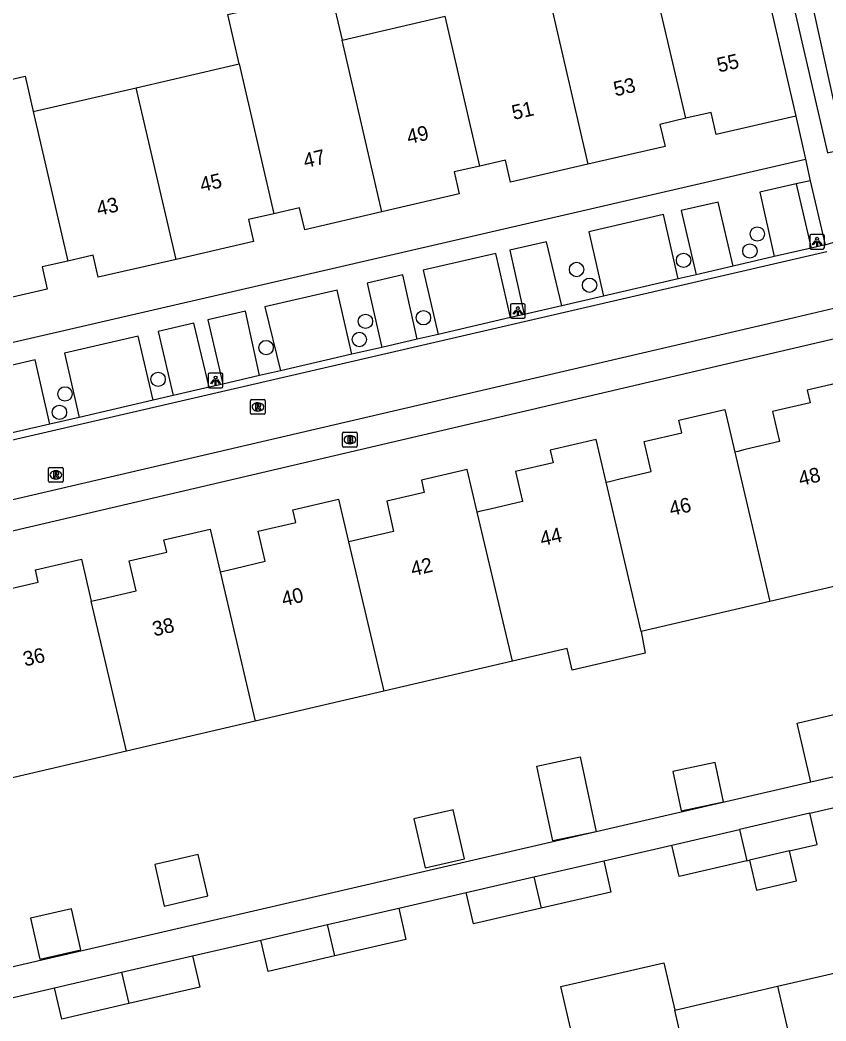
# Model space of a CAD drawing. Extents: x 156414 to 157775, y 382335 to 383765.
# Drawn here: x 156870.8 to 156925.8, y 382800.7 to 382868.8 of the extents above; entities that cross this region are included whole.
import ezdxf

# ---------------------------------------------------------------- set-up
doc = ezdxf.new("R2010")
doc.units = 0
for name, color, linetype in [('IMGEO_Boom', 7, 'Continuous'), ('IMGEO_Brandkraan', 7, 'Continuous'), ('IMGEO_Greppel_droge_sloot', 7, 'Continuous'), ('IMGEO_Lichtpunt', 7, 'Continuous'), ('IMGEO_Pand', 7, 'Continuous'), ('IMGEO_Pand_nummerreeks', 7, 'Continuous'), ('IMGEO_Rijbaan_lokaal_gesloten', 7, 'Continuous'), ('IMGEO_Rijbaan_lokaal_open', 7, 'Continuous'), ('IMGEO_Rioolput', 7, 'Continuous'), ('IMGEO_Voetpad_open', 7, 'Continuous')]:
    doc.layers.add(name, color=color, linetype=linetype)

msp = doc.modelspace()

# ---------------------------------------------------------------- linework, layer by layer
at = {"layer": 'IMGEO_Boom'}
for centre in [(156921.071, 382854.259), (156920.564, 382853.097), (156916.047, 382852.464), (156908.759, 382851.838), (156909.641, 382850.77), (156894.376, 382848.311), (156898.324, 382848.554), (156893.96, 382847.07), (156887.605, 382846.519), (156880.252, 382844.36), (156873.905, 382843.364), (156873.528, 382842.108)]:
    msp.add_circle(centre, 0.489, dxfattribs=at)
at = {"layer": 'IMGEO_Brandkraan'}
for p, q in [((156892.816, 382839.823), (156892.816, 382840.675)), ((156892.891, 382840.749), (156893.743, 382840.749)), ((156893.304, 382840.529), (156893.329, 382840.529)), ((156893.817, 382840.675), (156893.817, 382839.823)), ((156893.743, 382839.749), (156892.891, 382839.749)), ((156893.327, 382839.969), (156893.302, 382839.969))]:
    msp.add_line(p, q, dxfattribs=at)
for points in [[(156892.816, 382839.823), (156892.816, 382840.675)], [(156892.891, 382840.749), (156893.743, 382840.749)], [(156893.164, 382840.449), (156893.164, 382840.049), (156893.377, 382840.049)], [(156893.395, 382840.449), (156893.164, 382840.449)], [(156893.343, 382840.368), (156893.289, 382840.368), (156893.289, 382840.292)], [(156893.289, 382840.292), (156893.342, 382840.292)], [(156893.817, 382840.675), (156893.817, 382839.823)], [(156893.743, 382839.749), (156892.891, 382839.749)], [(156893.351, 382840.216), (156893.289, 382840.216), (156893.289, 382840.135)], [(156893.289, 382840.135), (156893.351, 382840.135)]]:
    msp.add_lwpolyline(points, dxfattribs=at)
for centre, radius, start, end in [((156892.893, 382840.673), 0.0765, 91.55205, 178.44795), ((156892.893, 382840.673), 0.0765, 91.55205, 178.44795), ((156893.344, 382840.33), 0.0379, 267.82845, 90.93552), ((156893.399, 382840.304), 0.145, 59.4692, 91.53667), ((156893.424, 382840.351), 0.0922, 285.51372, 58.15012), ((156893.429, 382840.159), 0.105, 301.31148, 78.98903), ((156893.741, 382840.673), 0.0765, 1.55205, 88.44795), ((156893.741, 382840.673), 0.0765, 1.55205, 88.44795), ((156892.893, 382839.825), 0.0765, 181.55205, 268.44795), ((156892.893, 382839.825), 0.0765, 181.55205, 268.44795), ((156893.352, 382840.175), 0.0404, 269.87594, 90.50774), ((156893.383, 382840.3), 0.251, 268.66757, 293.53466), ((156893.741, 382839.825), 0.0765, 271.55205, 358.44795), ((156893.741, 382839.825), 0.0765, 271.55205, 358.44795)]:
    msp.add_arc(centre, radius, start, end, dxfattribs=at)
for centre, major_axis, ratio, start_param, end_param in [((156893.303, 382840.249), (-0.387, 0.002), 0.722429, 4.712389, 7.853982), ((156893.328, 382840.249), (-0.39, 0.002), 0.717154, 1.570796, 4.712389)]:
    msp.add_ellipse(centre, major_axis=major_axis, ratio=ratio, start_param=start_param, end_param=end_param, dxfattribs=at)
at = {"layer": 'IMGEO_Greppel_droge_sloot'}
msp.add_lwpolyline([(156928.493, 382863.788), (156926.278, 382863.313), (156915.815, 382910.793), (156917.946, 382911.213), (156924.219, 382883.281), (156928.493, 382863.788)], dxfattribs=at)
at = {"layer": 'IMGEO_Lichtpunt'}
for p, q in [((156924.645, 382854.133), (156924.645, 382853.326)), ((156924.645, 382854.133), (156924.645, 382853.326)), ((156925.547, 382854.228), (156924.739, 382854.228)), ((156925.547, 382854.228), (156924.739, 382854.228)), ((156925.641, 382853.326), (156925.641, 382854.133)), ((156925.641, 382853.326), (156925.641, 382854.133)), ((156924.739, 382853.232), (156925.547, 382853.232)), ((156924.739, 382853.232), (156925.547, 382853.232)), ((156904.256, 382849.415), (156904.256, 382848.608)), ((156904.256, 382849.415), (156904.256, 382848.608)), ((156905.158, 382849.51), (156904.35, 382849.51)), ((156905.158, 382849.51), (156904.35, 382849.51)), ((156905.252, 382848.608), (156905.252, 382849.415)), ((156905.252, 382848.608), (156905.252, 382849.415)), ((156904.35, 382848.514), (156905.158, 382848.514)), ((156904.35, 382848.514), (156905.158, 382848.514)), ((156883.663, 382844.678), (156883.663, 382843.871)), ((156883.663, 382844.678), (156883.663, 382843.871)), ((156884.565, 382844.773), (156883.757, 382844.773)), ((156884.565, 382844.773), (156883.757, 382844.773)), ((156884.659, 382843.871), (156884.659, 382844.678)), ((156884.659, 382843.871), (156884.659, 382844.678)), ((156883.757, 382843.777), (156884.565, 382843.777)), ((156883.757, 382843.777), (156884.565, 382843.777))]:
    msp.add_line(p, q, dxfattribs=at)
for points in [[(156925.019, 382853.797), (156925.058, 382853.769), (156924.87, 382853.507), (156924.832, 382853.534), (156925.019, 382853.797)], [(156925.121, 382853.749), (156925.168, 382853.749), (156925.168, 382853.427), (156925.121, 382853.427), (156925.121, 382853.749)], [(156925.231, 382853.769), (156925.269, 382853.796), (156925.456, 382853.534), (156925.417, 382853.506), (156925.231, 382853.769)], [(156904.63, 382849.079), (156904.669, 382849.051), (156904.481, 382848.789), (156904.443, 382848.816), (156904.63, 382849.079)], [(156904.732, 382849.031), (156904.779, 382849.031), (156904.779, 382848.709), (156904.732, 382848.709), (156904.732, 382849.031)], [(156904.842, 382849.051), (156904.88, 382849.078), (156905.067, 382848.816), (156905.028, 382848.788), (156904.842, 382849.051)], [(156884.037, 382844.342), (156884.076, 382844.314), (156883.888, 382844.052), (156883.85, 382844.079), (156884.037, 382844.342)], [(156884.249, 382844.314), (156884.287, 382844.341), (156884.474, 382844.079), (156884.435, 382844.051), (156884.249, 382844.314)], [(156884.139, 382844.294), (156884.186, 382844.294), (156884.186, 382843.972), (156884.139, 382843.972), (156884.139, 382844.294)]]:
    msp.add_lwpolyline(points, dxfattribs=at)
for centre in [(156925.144, 382853.931), (156904.755, 382849.213), (156884.162, 382844.476)]:
    msp.add_circle(centre, 0.0994, dxfattribs=at)
for centre, start, end in [((156924.739, 382854.133), 90, 180), ((156924.739, 382854.133), 90, 180), ((156925.547, 382854.133), 0, 90), ((156925.547, 382854.133), 0, 90), ((156924.739, 382853.326), 180, 270), ((156924.739, 382853.326), 180, 270), ((156925.547, 382853.326), 270, 0), ((156925.547, 382853.326), 270, 360), ((156904.35, 382849.415), 90, 180), ((156904.35, 382849.415), 90, 180), ((156905.158, 382849.415), 0, 90), ((156905.158, 382849.415), 0, 90), ((156904.35, 382848.608), 180, 270), ((156904.35, 382848.608), 180, 270), ((156905.158, 382848.608), 270, 0), ((156905.158, 382848.608), 270, 360), ((156883.757, 382844.678), 90, 180), ((156883.757, 382844.678), 90, 180), ((156884.565, 382844.678), 0, 90), ((156884.565, 382844.678), 0, 90), ((156883.757, 382843.871), 180, 270), ((156883.757, 382843.871), 180, 270), ((156884.565, 382843.871), 270, 0), ((156884.565, 382843.871), 270, 360)]:
    msp.add_arc(centre, 0.0946, start, end, dxfattribs=at)
at = {"layer": 'IMGEO_Pand'}
for points in [[(156920.983, 382873.977), (156923.698, 382862.279)], [(156916.198, 382862.134), (156913.825, 382872.323)], [(156885.771, 382865.841), (156884.991, 382869.213), (156892.002, 382870.835), (156892.785, 382867.461)], [(156906.812, 382870.703), (156909.525, 382859.004)], [(156892.785, 382867.461), (156899.798, 382869.082)], [(156902.17, 382858.884), (156899.798, 382869.082)], [(156895.499, 382855.764), (156892.785, 382867.461)], [(156878.757, 382864.22), (156885.771, 382865.841)], [(156885.771, 382865.841), (156888.131, 382855.638)], [(156864.73, 382860.979), (156864.176, 382863.373), (156871.189, 382864.996), (156871.744, 382862.599)], [(156871.744, 382862.599), (156878.757, 382864.22)], [(156881.472, 382852.525), (156878.757, 382864.22)], [(156871.744, 382862.599), (156874.101, 382852.413)], [(156916.198, 382862.134), (156914.437, 382861.725), (156914.785, 382860.225), (156909.525, 382859.004)], [(156923.698, 382862.279), (156918.273, 382861.034), (156917.925, 382862.535), (156916.198, 382862.134)], [(156902.17, 382858.884), (156900.41, 382858.482), (156900.758, 382856.982), (156895.499, 382855.764)], [(156909.525, 382859.004), (156904.262, 382857.782), (156903.914, 382859.282), (156902.17, 382858.884)], [(156895.499, 382855.764), (156890.24, 382854.546), (156889.893, 382856.046), (156888.131, 382855.638)], [(156888.131, 382855.638), (156886.405, 382855.239), (156886.753, 382853.738), (156881.472, 382852.525)], [(156881.472, 382852.525), (156876.163, 382851.306), (156875.818, 382852.806), (156874.101, 382852.413)], [(156874.101, 382852.413), (156872.343, 382852.01), (156872.69, 382850.509), (156867.434, 382849.292)], [(156927.788, 382844.392), (156924.464, 382843.616), (156924.664, 382842.759), (156922.103, 382842.162), (156922.58, 382840.117), (156920.242, 382839.571), (156919.736, 382839.453), (156919.531, 382839.405)], [(156910.781, 382837.356), (156911.003, 382837.408), (156911.695, 382837.571), (156913.846, 382838.076), (156913.366, 382840.12), (156915.927, 382840.721), (156915.726, 382841.578), (156918.85, 382842.311), (156919.531, 382839.405)], [(156910.781, 382837.356), (156910.101, 382840.268), (156906.957, 382839.533), (156907.158, 382838.676), (156904.597, 382838.078), (156905.075, 382836.033), (156902.877, 382835.519), (156902.231, 382835.368), (156901.988, 382835.311)], [(156919.531, 382839.405), (156921.915, 382829.231)], [(156901.988, 382835.311), (156901.301, 382838.221), (156898.186, 382837.5), (156898.385, 382836.643), (156895.822, 382836.05), (156896.296, 382834.004), (156894.3, 382833.542), (156893.451, 382833.345), (156893.227, 382833.293)], [(156913.155, 382827.194), (156910.781, 382837.356)], [(156884.473, 382831.247), (156884.71, 382831.302), (156885.471, 382831.48), (156887.553, 382831.965), (156887.077, 382834.01), (156889.638, 382834.608), (156889.438, 382835.465), (156892.545, 382836.189), (156893.227, 382833.293)], [(156904.385, 382825.154), (156901.988, 382835.311)], [(156875.698, 382829.25), (156875.9, 382829.296), (156876.422, 382829.415), (156878.747, 382829.944), (156878.28, 382831.992), (156880.845, 382832.576), (156880.649, 382833.434), (156883.79, 382834.15), (156884.473, 382831.247)], [(156893.227, 382833.293), (156895.625, 382823.117)], [(156866.935, 382827.191), (156867.151, 382827.241), (156867.738, 382827.376), (156869.996, 382827.897), (156869.524, 382829.944), (156872.086, 382830.535), (156871.889, 382831.393), (156875.024, 382832.117), (156875.698, 382829.25)], [(156884.473, 382831.247), (156886.866, 382821.08)], [(156930.84, 382831.306), (156921.915, 382829.231)], [(156878.096, 382819.04), (156875.698, 382829.25)], [(156921.915, 382829.231), (156913.155, 382827.194)], [(156913.155, 382827.194), (156913.44, 382825.7), (156908.457, 382824.541), (156908.113, 382826.021), (156904.385, 382825.154)], [(156904.385, 382825.154), (156895.625, 382823.117)], [(156895.625, 382823.117), (156886.866, 382821.08)], [(156924.725, 382816.92), (156923.79, 382820.948), (156926.665, 382821.615), (156927.6, 382817.588)], [(156886.866, 382821.08), (156878.096, 382819.04)], [(156878.096, 382819.04), (156869.326, 382817.001)], [(156910.089, 382813.546), (156907.132, 382812.917), (156906.049, 382818.014), (156909.006, 382818.642), (156910.089, 382813.546)], [(156915.323, 382817.649), (156915.892, 382814.972), (156918.773, 382815.585), (156918.204, 382818.262), (156915.323, 382817.649)], [(156927.6, 382817.588), (156924.725, 382816.92)], [(156897.681, 382814.428), (156898.452, 382811.093), (156901.129, 382811.711), (156900.359, 382815.046), (156897.681, 382814.428)], [(156924.651, 382814.81), (156919.855, 382813.702)], [(156923.265, 382812.238), (156925.145, 382812.672), (156924.651, 382814.81)], [(156915.259, 382812.64), (156919.855, 382813.702)], [(156919.855, 382813.702), (156920.351, 382811.565)], [(156920.351, 382811.565), (156915.752, 382810.503), (156915.259, 382812.64)], [(156880.02, 382811.313), (156880.672, 382808.488), (156883.631, 382809.171), (156882.978, 382811.996), (156881.026, 382811.545), (156880.02, 382811.313)], [(156923.265, 382812.238), (156920.55, 382811.611)], [(156920.55, 382811.611), (156921.026, 382809.562), (156923.74, 382810.192), (156923.265, 382812.238)], [(156905.843, 382810.464), (156910.611, 382811.566)], [(156910.611, 382811.566), (156911.103, 382809.434), (156906.335, 382808.333)], [(156920.351, 382811.565), (156920.55, 382811.611)], [(156901.237, 382809.4), (156905.843, 382810.464)], [(156905.843, 382810.464), (156906.335, 382808.333)], [(156906.335, 382808.333), (156901.729, 382807.27), (156901.237, 382809.4)], [(156871.551, 382807.654), (156872.195, 382804.867), (156874.983, 382805.51), (156874.339, 382808.298), (156871.551, 382807.654)], [(156891.793, 382807.218), (156896.638, 382808.337)], [(156896.638, 382808.337), (156897.131, 382806.203), (156892.289, 382805.084)], [(156887.245, 382806.167), (156891.793, 382807.218)], [(156892.289, 382805.084), (156891.793, 382807.218)], [(156892.289, 382805.084), (156887.738, 382804.033), (156887.245, 382806.167)], [(156877.753, 382803.974), (156882.588, 382805.091)], [(156882.588, 382805.091), (156883.082, 382802.956), (156878.25, 382801.84)], [(156908.428, 382799.782), (156907.686, 382802.997), (156914.697, 382804.615), (156915.442, 382801.401)], [(156922.45, 382803.019), (156929.471, 382804.64)], [(156873.186, 382802.919), (156877.753, 382803.974)], [(156877.753, 382803.974), (156878.25, 382801.84)], [(156878.25, 382801.84), (156873.679, 382800.784), (156873.186, 382802.919)], [(156915.442, 382801.401), (156922.45, 382803.019)], [(156922.45, 382803.019), (156925.163, 382791.326)], [(156917.48, 382792.603), (156915.442, 382801.401)]]:
    msp.add_lwpolyline(points, dxfattribs=at)
at = {"layer": 'IMGEO_Rijbaan_lokaal_gesloten'}
for points in [[(156704.67, 382802.003), (156706.623, 382802.451), (156776.982, 382818.697), (156816.178, 382827.739), (156855.39, 382836.785), (156925.817, 382853.068)], [(156926.664, 382849.268), (156923.197, 382848.454), (156856.378, 382832.904), (156817.084, 382823.811), (156780.281, 382815.295), (156707.464, 382798.538)]]:
    msp.add_lwpolyline(points, dxfattribs=at)
at = {"layer": 'IMGEO_Rijbaan_lokaal_open'}
for points in [[(156925.683, 382853.514), (156926.283, 382853.698), (156926.76, 382853.92), (156927.263, 382854.185), (156927.472, 382854.33)], [(156924.736, 382853.295), (156922.218, 382852.713)], [(156925.683, 382853.514), (156924.736, 382853.295)], [(156922.218, 382852.713), (156919.436, 382852.07)], [(156919.436, 382852.07), (156916.897, 382851.483)], [(156915.69, 382851.204), (156910.6, 382850.027)], [(156916.897, 382851.483), (156915.69, 382851.204)], [(156910.6, 382850.027), (156907.756, 382849.369)], [(156907.756, 382849.369), (156905.196, 382848.777)], [(156904.266, 382848.562), (156899.333, 382847.422)], [(156905.196, 382848.777), (156904.266, 382848.562)], [(156897.895, 382847.09), (156895.49, 382846.533)], [(156899.333, 382847.422), (156897.895, 382847.09)], [(156895.49, 382846.533), (156893.454, 382846.063)], [(156893.454, 382846.063), (156888.588, 382844.938)], [(156887.16, 382844.608), (156884.659, 382844.029)], [(156888.588, 382844.938), (156887.16, 382844.608)], [(156883.73, 382843.815), (156881.278, 382843.248)], [(156884.659, 382844.029), (156883.73, 382843.815)], [(156881.278, 382843.248), (156879.923, 382842.934)], [(156879.923, 382842.934), (156874.877, 382841.768)], [(156874.877, 382841.768), (156872.882, 382841.306)], [(156872.882, 382841.306), (156868.022, 382840.183)]]:
    msp.add_lwpolyline(points, dxfattribs=at)
at = {"layer": 'IMGEO_Rioolput'}
for p, q in [((156886.547, 382842.05), (156886.547, 382842.902)), ((156886.622, 382842.976), (156887.474, 382842.976)), ((156887.035, 382842.756), (156887.06, 382842.756)), ((156887.548, 382842.902), (156887.548, 382842.05)), ((156887.474, 382841.976), (156886.622, 382841.976)), ((156887.058, 382842.196), (156887.033, 382842.196)), ((156872.783, 382837.422), (156872.783, 382838.274)), ((156872.858, 382838.348), (156873.71, 382838.348)), ((156873.784, 382838.274), (156873.784, 382837.422)), ((156873.294, 382837.568), (156873.269, 382837.568)), ((156873.271, 382838.128), (156873.296, 382838.128)), ((156873.71, 382837.348), (156872.858, 382837.348))]:
    msp.add_line(p, q, dxfattribs=at)
for points in [[(156886.547, 382842.05), (156886.547, 382842.902)], [(156886.622, 382842.976), (156887.474, 382842.976)], [(156887.136, 382842.674), (156886.884, 382842.676), (156886.884, 382842.276)], [(156886.884, 382842.276), (156887.008, 382842.276), (156887.008, 382842.438), (156887.019, 382842.438)], [(156887.062, 382842.595), (156887.008, 382842.595), (156887.008, 382842.514)], [(156887.008, 382842.514), (156887.06, 382842.514)], [(156887.066, 382842.409), (156887.137, 382842.276), (156887.277, 382842.276), (156887.212, 382842.402)], [(156887.548, 382842.902), (156887.548, 382842.05)], [(156887.474, 382841.976), (156886.622, 382841.976)], [(156872.783, 382837.422), (156872.783, 382838.274)], [(156872.858, 382838.348), (156873.71, 382838.348)], [(156873.784, 382838.274), (156873.784, 382837.422)], [(156873.372, 382838.046), (156873.12, 382838.048), (156873.12, 382837.648)], [(156873.12, 382837.648), (156873.244, 382837.648), (156873.244, 382837.81), (156873.255, 382837.81)], [(156873.298, 382837.967), (156873.244, 382837.967), (156873.244, 382837.886)], [(156873.244, 382837.886), (156873.296, 382837.886)], [(156873.302, 382837.781), (156873.373, 382837.648), (156873.513, 382837.648), (156873.448, 382837.774)], [(156873.71, 382837.348), (156872.858, 382837.348)]]:
    msp.add_lwpolyline(points, dxfattribs=at)
for centre, radius, start, end in [((156886.624, 382842.9), 0.0765, 91.55205, 178.44795), ((156886.624, 382842.9), 0.0765, 91.55205, 178.44795), ((156887.018, 382842.385), 0.0533, 26.02933, 88.69889), ((156887.044, 382842.703), 0.19, 274.7715, 282.96867), ((156887.068, 382842.499), 0.0964, 77.00612, 93.18647), ((156887.082, 382842.556), 0.0378, 276.66336, 79.67722), ((156887.135, 382842.564), 0.109, 350.36119, 89.41601), ((156887.133, 382842.564), 0.112, 277.58423, 350.98172), ((156887.117, 382842.349), 0.108, 29.51342, 73.79051), ((156887.472, 382842.9), 0.0765, 1.55205, 88.44795), ((156887.472, 382842.9), 0.0765, 1.55205, 88.44795), ((156886.624, 382842.052), 0.0765, 181.55205, 268.44795), ((156886.624, 382842.052), 0.0765, 181.55205, 268.44795), ((156887.472, 382842.052), 0.0765, 271.55205, 358.44795), ((156887.472, 382842.052), 0.0765, 271.55205, 358.44795), ((156872.86, 382838.272), 0.0765, 91.55205, 178.44795), ((156872.86, 382838.272), 0.0765, 91.55205, 178.44795), ((156873.708, 382838.272), 0.0765, 1.55205, 88.44795), ((156873.708, 382838.272), 0.0765, 1.55205, 88.44795), ((156873.254, 382837.757), 0.0533, 26.02933, 88.69889), ((156873.28, 382838.075), 0.19, 274.7715, 282.96867), ((156873.304, 382837.871), 0.0964, 77.00612, 93.18647), ((156873.318, 382837.928), 0.0378, 276.66336, 79.67722), ((156873.371, 382837.936), 0.109, 350.36119, 89.41601), ((156873.369, 382837.936), 0.112, 277.58423, 350.98172), ((156873.353, 382837.721), 0.108, 29.51342, 73.79051), ((156872.86, 382837.424), 0.0765, 181.55205, 268.44795), ((156872.86, 382837.424), 0.0765, 181.55205, 268.44795), ((156873.708, 382837.424), 0.0765, 271.55205, 358.44795), ((156873.708, 382837.424), 0.0765, 271.55205, 358.44795)]:
    msp.add_arc(centre, radius, start, end, dxfattribs=at)
for centre, major_axis, ratio, start_param, end_param in [((156887.034, 382842.476), (-0.387, 0.002), 0.722429, 4.712389, 7.853982), ((156887.059, 382842.476), (-0.39, 0.002), 0.717154, 1.570796, 4.712389), ((156873.27, 382837.848), (-0.387, 0.002), 0.722429, 4.712389, 7.853982), ((156873.295, 382837.848), (-0.39, 0.002), 0.717154, 1.570796, 4.712389)]:
    msp.add_ellipse(centre, major_axis=major_axis, ratio=ratio, start_param=start_param, end_param=end_param, dxfattribs=at)
at = {"layer": 'IMGEO_Voetpad_open'}
for points in [[(156920.762, 382881.795), (156925.852, 382859.789), (156930.181, 382860.808)], [(156923.698, 382862.279), (156924.352, 382859.349)], [(156853.925, 382843.103), (156924.352, 382859.349)], [(156924.352, 382859.349), (156924.67, 382857.885)], [(156923.715, 382857.664), (156921.249, 382857.094), (156922.218, 382852.713)], [(156924.67, 382857.885), (156923.715, 382857.664)], [(156923.715, 382857.664), (156924.736, 382853.295)], [(156924.67, 382857.885), (156925.683, 382853.514)], [(156919.436, 382852.07), (156918.398, 382856.435), (156915.892, 382855.856), (156916.897, 382851.483)], [(156915.69, 382851.204), (156914.687, 382855.577), (156909.589, 382854.399), (156910.6, 382850.027)], [(156907.756, 382849.369), (156906.704, 382853.731), (156904.204, 382853.154), (156905.196, 382848.777)], [(156904.266, 382848.562), (156903.257, 382852.935), (156898.314, 382851.792), (156899.333, 382847.422)], [(156897.895, 382847.09), (156896.927, 382851.471), (156894.491, 382850.908), (156895.49, 382846.533)], [(156893.454, 382846.063), (156892.453, 382850.437), (156887.527, 382849.298), (156888.588, 382844.938)], [(156887.16, 382844.608), (156886.198, 382848.991), (156883.636, 382848.399), (156884.659, 382844.029)], [(156883.73, 382843.815), (156882.692, 382848.18), (156880.264, 382847.619), (156881.278, 382843.248)], [(156856.714, 382830.844), (156856.91, 382830.891), (156859.126, 382831.425), (156927.114, 382847.315)], [(156879.923, 382842.934), (156878.9, 382847.303), (156873.868, 382846.14), (156874.877, 382841.768)], [(156872.882, 382841.306), (156871.879, 382845.68), (156866.991, 382844.55), (156868.022, 382840.183)], [(156924.725, 382816.92), (156910.089, 382813.546)], [(156924.651, 382814.81), (156929.454, 382815.919)], [(156910.089, 382813.546), (156866.124, 382803.38)], [(156910.611, 382811.566), (156915.259, 382812.64)], [(156896.638, 382808.337), (156901.237, 382809.4)], [(156882.588, 382805.091), (156887.245, 382806.167)], [(156868.402, 382801.813), (156873.186, 382802.919)]]:
    msp.add_lwpolyline(points, dxfattribs=at)

# ---------------------------------------------------------------- texts
at = {"layer": 'IMGEO_Pand_nummerreeks'}
for s, rotation, p in [('55', 13.01047, (156918.451, 382865.25)), ('53', 13.01047, (156911.405, 382863.622)), ('51', 13.01047, (156904.47, 382862.019)), ('49', 13.01047, (156897.314, 382860.366)), ('47', 13.01187, (156890.27, 382858.738)), ('45', 13.01047, (156883.223, 382857.11)), ('43', 13.01047, (156876.178, 382855.482)), ('48', 13.09782, (156924.005, 382837.085)), ('46', 13.09782, (156915.197, 382835.036)), ('44', 13.09782, (156906.393, 382832.987)), ('42', 13.09782, (156897.586, 382830.938)), ('40', 13.09782, (156888.787, 382828.892)), ('38', 13.09782, (156879.983, 382826.843)), ('36', 13.09782, (156871.176, 382824.794))]:
    msp.add_text(s, height=1, rotation=rotation, dxfattribs=at).set_placement(p)

doc.saveas('drawing.dxf')
